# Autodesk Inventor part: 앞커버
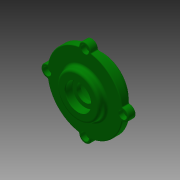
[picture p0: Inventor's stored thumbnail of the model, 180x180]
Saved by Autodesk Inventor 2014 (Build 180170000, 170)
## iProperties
Created: 2016-05
Part Number: 앞커버
Document SubType Name: Modeling
Designer: mduedu
Density: 2.71 g/cm^3
Material: 알루미늄 6061
Appearance: Dark Green
Author: mduedu
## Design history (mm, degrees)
sketch "스케치1"
  geometry: C1 r 32 at (0, 0); C2 r 44 at (0, 0); 1 further point
  constraints: 2 centre point, 2 coincident
  dimensions: "d33" = 88 diameter of C2; "d34" = 64 diameter of C1
extrude "돌출1" new body sketch "스케치1" distance "d0" = 8; taper "d1" = 0 deg
extrude "돌출2" join sketch "스케치1" distance "d2" = 8; taper "d3" = 0 deg; dims "d35" = 12, "d36" = 0
sketch "스케치6"
  geometry: C1 r 25 at (0, 0); 2 further points
  constraints: 2 coincident, 1 centre point
  dimensions: "d42" = 50 diameter of C1
extrude "돌출4" join sketch "스케치6" distance "d43" = 8; taper "d44" = 0 deg
sketch "스케치9"
  geometry: C1 r 7 at (0, 44); 2 further points
  constraints: 2 vertical alignment, 1 centre point, 1 other
  dimensions: "d70" = 14 diameter of C1
extrude "돌출5" join sketch "스케치9" stored distance "d71" = 10; taper "d72" = 0 deg
fillet "모깎기9" dims "d76" = 1
sketch "스케치10"
  geometry: C1 r 25 at (0, 0) reference; A1 r 1 centre (-44.284, 7.995) between (-44.249, 6.996) and (-43.3, 7.817) reference; A2 r 7 centre (-44, 0) between (-44.249, 6.996) and (-44.249, -6.996) reference; A3 r 1 centre (-44.284, -7.995) between (-43.3, -7.817) and (-44.249, -6.996) reference; A4 r 44 centre (0, 0) between (-43.3, -7.817) and (-7.817, -43.3) reference; A5 r 1 centre (-7.995, -44.284) between (-6.996, -44.249) and (-7.817, -43.3) reference; A6 r 7 centre (0, -44) between (-6.996, -44.249) and (6.996, -44.249) reference; A7 r 1 centre (7.995, -44.284) between (7.817, -43.3) and (6.996, -44.249) reference; A8 r 1 centre (7.995, 44.284) between (6.996, 44.249) and (7.817, 43.3) reference; A9 r 7 centre (0, 44) between (6.996, 44.249) and (-6.996, 44.249) reference; A10 r 1 centre (-7.995, 44.284) between (-7.817, 43.3) and (-6.996, 44.249) reference; A11 r 7 centre (44, 0) between (44.249, -6.996) and (44.249, 6.996) reference; A12 r 44 centre (0, 0) between (-7.817, 43.3) and (-43.3, 7.817) reference; A13 r 44 centre (0, 0) between (7.817, -43.3) and (43.3, -7.817) reference; A14 r 1 centre (44.284, -7.995) between (44.249, -6.996) and (43.3, -7.817) reference; A15 r 1 centre (44.284, 7.995) between (43.3, 7.817) and (44.249, 6.996) reference; A16 r 44 centre (0, 0) between (43.3, 7.817) and (7.817, 43.3) reference; 4 further points
  constraints: 3 coincident
hole "구멍3" sketch "스케치10" at (0, 44), (-44, 0), (0, -44), (44, 0) diameter "d77" = 5.5; stored, may be unused: countersink angle "d81" = 90 deg, drill point angle "d83" = 118 deg; dims "d78" = 6, "d79" = 9.5, "d80" = 5.4, "d82" = 8
fillet "모깎기10" dims "d84" = 1
fillet "모깎기7" dims "d68" = 3
fillet "모깎기8" dims "d69" = 3
sketch "스케치4"
  geometry: L1 (0, -12)-(0, 16); L2 (-20, -12)-(-20, 0); L3 (-20, 0)-(-15, 0); L4 (-15, 0)-(-15, 3); L5 (-15, 3)-(-10, 3); L6 (-10, 3)-(-10, 7.7); L7 (-10, 7.7)-(-15, 7.7); L8 (-15, 7.7)-(-15, 16); L9 (32, -12)-(-32, -12) reference; L10 (25, 16)-(-25, 16) reference; 1 further point
  constraints: 16 end point, 6 parallel, 3 point on line, 2 midpoint, 1 perpendicular, 1 vertical
  dimensions: "d15" = 40 diameter of L2 L1; "d16" = 30 diameter of L8 L1; "d18" = 12 distance of L2.start L2.end; "d19" = 3 distance of L3.end L4.end; "d20" = 30 diameter of L4 L1; "d21" = 20 diameter of L6 L1; "d45" = 8.3 distance of L7.end L8.end
revolve "회전1" sketch "스케치4" stored, may be unused: angle "d22" = 90 deg
fillet "모깎기2" dims "d23" = 3
fillet "모깎기3" dims "d24" = 0.3
chamfer "모따기2" distance "d46" = 1; stored, may be unused: second distance "d47" = 2, angle "d48" = 45 deg
chamfer "모따기3" distance "d64" = 0.8; stored, may be unused: second distance "d65" = 2, angle "d66" = 30 deg
node "솔리드1"
pattern_circular "원형 패턴1" dims angle "d74" = 360 deg
node "투영된 루프1"
